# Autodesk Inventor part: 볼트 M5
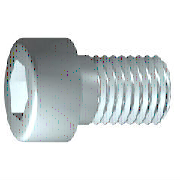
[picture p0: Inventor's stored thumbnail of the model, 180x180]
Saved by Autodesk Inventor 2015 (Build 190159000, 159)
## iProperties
IsCustomPart: 1
Created: 2012-02
Part Number: 볼트 M5
Material: 강철, 연강
Description: 6각머리 태핑 나사
Document SubType Name: Modeling
Standard: KS B 1003
Designer: mduedu
Standards Organization: KS
Language: ko-KR
Size Designation: M 5 x 12
Categories: <MemberInstance><Categories><Category DisplayName="조임쇠" InternalName="e4da775c-781d-43d5-af7c-5136215cf5a6" Mnemonic="FSTN"><Category DisplayName="볼트" InternalN
Density: 1 g/cm^3
Appearance: 강철
Author: mduedu
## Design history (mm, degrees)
sketch "스케치1"
  geometry: L1 (-1.167, 0)-(12, 0); L2 (12, 0)-(12, 2.5); L3 (12, 2.5)-(2, 2.5); L4 (2, 2.5)-(1.509, 2.5); L5 (1.509, 2.5)-(0, 2.5); L6 (0, 2.5)-(0, 4.25); L7 (0, 4.25)-(-5, 4.25); L8 (-5, 4.25)-(-5, 2.309); L9 (-5, 2.309)-(-2.5, 2.309); L10 (-2.5, 2.309)-(-1.167, 0); L11 (-8.4, 0)-(15.4, 0) reference; L12 (0, -0.85)-(0, 5.1) reference; L13 (2, 2.5)-(0, 2.5)
  constraints: 22 end point, 6 parallel, 2 collinear, 2 perpendicular, 1 horizontal, 1 point on line
  dimensions: "d1" = 10 distance from line of L3.end L2 (= GEL); "d2" = 0.49086 distance of L4.end L3.end (computed from GAL); "d3" = 5 distance between parallel lines of L8 L6 (= KOH); "d4" = 2.5 distance of L8.end L9.end (= INTI); "d5" = 60 deg angle of L10 L1; "d6" = 5 diameter of L3 L1 (= GD); "d7" = 5 diameter of L5 L1 (= BDM); "d8" = 4.6188 diameter of L9 L1 (= 1.1547 x SW); "d9" = 8.5 diameter of L7 L1 (= KOD); "d26" = 12 distance between parallel lines of L12 L2 (= NLG)
revolve "본체" sketch "스케치1" stored, may be unused: angle "d10" = 90 deg
sketch "스케치2"
  geometry: L1 (0, -5.95)-(0, 5.95) reference; L2 (-5.95, 0)-(5.95, 0) reference; L3 (2.309, 0)-(1.155, -2); L4 (1.155, -2)-(-1.155, -2); L5 (-1.155, -2)-(-2.309, 0); L6 (-2.309, 0)-(-1.155, 2); L7 (-1.155, 2)-(1.155, 2); L8 (1.155, 2)-(2.309, 0); 2 further points
  constraints: 12 end point, 1 coincident, 1 horizontal alignment, 1 point on line, 12 other
extrude "슬롯" join sketch "스케치2" stored distance "d11" = 10; taper "d12" = 0 deg
workplane "Work Plane1"
fillet "Fillet2" dims "d30" = 0.1 (= R)
body "Solid1"
fillet "모깎기1" dims "d17" = 0.5 (= RR)
feature "스레드" dims "d13" = 10 (= GEL), "d14" = 0
chamfer "모따기1" distance "d15" = 0.49076 (= -0.5 x SPD + 0.5 x GD); stored, may be unused: second distance "d16" = 0.49076 (= GUL), angle "d27" = 45 deg
other parameters: "GD" = 5 (= NND) [user parameter; used in 2 equation terms], "NLG" = 12 [user parameter; used in 1 equation term], "GEL" = 10 [user parameter; used in 2 equation terms], "KOD" = 8.5 [user parameter; used in 1 equation term], "KOH" = 5 [user parameter; used in 1 equation term], "INTI" = 2.5 [user parameter; used in 1 equation term], "GAL" = 0.49076 (= 0.61345 x PTC) [user parameter; used in 1 equation term], "GUL" = 0.49076 (= 0.61345 x PTC) [user parameter; used in 1 equation term], "BDM" = 5 (= NND) [user parameter; used in 1 equation term], "SW" = 4 [user parameter; used in 2 equation terms], "RR" = 0.5 [user parameter; used in 1 equation term], "SPD" = 4.01848 (= NND - 1.2269 x PTC) [user parameter; used in 1 equation term], "d19" = 0, "d28" = 0, "d29" = 0, "R" = 0.1 [user parameter; used in 1 equation term], "PHH" = 0.2 [user parameter], "GD1" = 4.01848 (= THREADDIA - 1.2269 x PTC) [user parameter], "THREADDIA" = 5 [user parameter; used in 1 equation term], "FAWI" = 45 deg [user parameter], "TPU" = 12.5 (computed from PTC) [user parameter], "PTC" = 0.8 [user parameter; used in 5 equation terms], "NND" = 5 [user parameter; used in 3 equation terms], "TOA" = 30 deg [user parameter], "E0" = 4.62 (= 1.155 x SW) [user parameter]
